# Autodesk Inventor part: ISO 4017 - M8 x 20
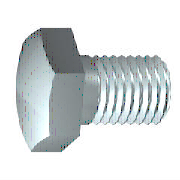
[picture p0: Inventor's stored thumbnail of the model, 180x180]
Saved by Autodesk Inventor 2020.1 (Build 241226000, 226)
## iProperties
Manager: www.cadconsulting.pl
Company: Fabian Stasiak CAD Consulting
Created: 2010-02
Part Number: ISO 4017 - M8 x 20
Material: Stal nierdzewna, 440C
Description: Wkręty z łbem sześciokątnym
Document SubType Name: Modeling
Standard: ISO 4017
Designer: F.Stasiak
Standard Revision: Third edition 1999-08-15
Standards Organization: ISO
Language: pl-PL
Size Designation: M8 x 20
Categories: <MemberInstance><Categories><Category DisplayName="Mocowania" InternalName="e4da775c-781d-43d5-af7c-5136215cf5a6" Mnemonic="FSTN"><Category DisplayName="Śruby"
Density: 7.75 g/cm^3
Appearance: Metal-Stal
IsCustomPart: 0
Author: F.Stasiak
Subject: Zbiór ćwiczeń. Autodesk Inventor 2020. Kurs podstawowy
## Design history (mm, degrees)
sketch "Sketch1"
  geometry: L1 (0, 5.815)-(0, 4); L2 (4, 4)-(20, 4); L3 (20, 4)-(20, 0); L4 (20, 0)-(-0.6, 0); L5 (-4.72, 0)-(24.12, 0) reference; L6 (-0.6, 0)-(-0.6, 5.815); L7 (-0.6, 5.815)-(0, 5.815); L8 (4, 4)-(3.233, 4); L9 (3.233, 4)-(0, 4); L10 (0, -1.163)-(0, 6.978) reference
  constraints: 16 end point, 2 collinear, 2 perpendicular, 1 parallel
  dimensions: "d0" = 20 distance between parallel lines of L3 L1 (= NLG); "d1" = 16 distance from line of L2.start L3 (= GEL); "d2" = 8 diameter of L2 L4 (= GD); "d9" = 0.6001 distance between parallel lines of L6 L1 (computed from SD); "d10" = 11.63 diameter of L7 L4 (= SD2); "d13" = 0.76691 distance of L2.start L8.end (computed from GAL); "d14" = 8 diameter of L9 L4 (= BDM)
revolve "Body" sketch "Sketch1" stored, may be unused: angle "d12" = 90 deg
sketch "Sketch2"
  geometry: L1 (0, 7.506)-(6.5, 3.753); L2 (6.5, 3.753)-(6.5, -3.753); L3 (6.5, -3.753)-(0, -7.506); L4 (0, -7.506)-(-6.5, -3.753); L5 (-6.5, -3.753)-(-6.5, 3.753); L6 (-6.5, 3.753)-(0, 7.506); 2 further points
  constraints: 12 end point, 1 coincident, 1 vertical, 11 other
  dimensions: "d11" = 13 distance between parallel lines of L5 L2 (= SW)
extrude "Head" join sketch "Sketch2" distance "d3" = 4.7 (= KOH - SD); taper "d4" = 0 deg
sketch "Sketch4"
  geometry: L1 (-5.3, 6.5)-(-5.3, 7.506); L2 (-5.3, 7.506)-(-4.72, 7.506); L3 (-4.72, 7.506)-(-5.3, 6.5); L4 (-6.24, 0)-(0.34, 0) reference; L5 (-0.6, 7.506)-(-5.3, 7.506) reference; L6 (-5.3, 3.753)-(-5.3, 7.506) reference
  constraints: 6 end point, 2 collinear, 1 perpendicular, 1 vertical
  dimensions: "d5" = 30 deg angle of L3 L1 (= ANG1); "d19" = 13 diameter of L1.start L4 (= SW0)
revolve "Chamfer1" sketch "Sketch4" stored, may be unused: angle "d21" = 90 deg
feature "Thread" dims "d15" = 16 (= GEL), "d16" = 0
chamfer "Chamfer2" distance "d6" = 0.76681 (= -0.5 x SPD + 0.5 x GD); stored, may be unused: second distance "d7" = 0.76691 (computed from GUL), angle "d55" = 45 deg
workplane "Work Plane1"
body "Solid1"
other parameters: "NLG" = 20 [user parameter; used in 1 equation term], "GD" = 8 (= NND) [user parameter; used in 2 equation terms], "BDM" = 8 (= NND) [user parameter; used in 1 equation term], "KOH" = 5.3 [user parameter; used in 1 equation term], "GEL" = 16 [user parameter; used in 2 equation terms], "SW" = 13 [user parameter; used in 2 equation terms], "SW0" = 13 (= SW) [user parameter; used in 1 equation term], "SPD" = 6.46637 (= NND - 1.2269 x PTC) [user parameter; used in 1 equation term], "SD2" = 11.63 [user parameter; used in 2 equation terms], "SD" = 0.6 [user parameter; used in 2 equation terms], "ANG1" = 30 deg [user parameter; used in 1 equation term], "GAL" = 0.76681 (= 0.61345 x PTC) [user parameter; used in 1 equation term], "GUL" = 0.76681 (= 0.61345 x PTC) [user parameter; used in 1 equation term], "d8" = 0, "RR" = 0.4 [user parameter], "d57" = 0, "d58" = 0, "TPU" = 8 (computed from PTC) [user parameter], "GD1" = 6.46637 (= THREADDIA - 1.2269 x PTC) [user parameter], "THREADDIA" = 8 [user parameter; used in 1 equation term], "SDH" = 11.63 (= SD2) [user parameter], "SDHG" = 4 [user parameter], "TOA" = 30 deg [user parameter], "PTC" = 1.25 [user parameter; used in 5 equation terms], "NND" = 8 [user parameter; used in 3 equation terms], "E0" = 15.015 [user parameter]
